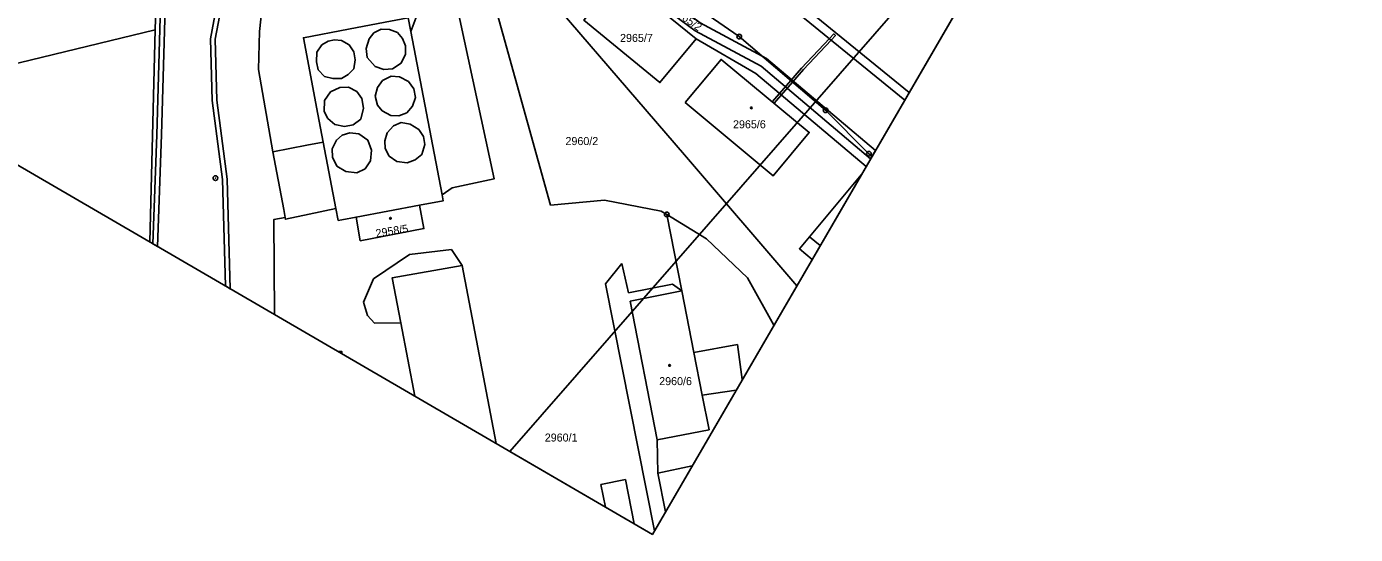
# Model space of a CAD drawing. Extents: x -621168 to -620292, y -1122748 to -1122069.
# Drawn here: x -620574.6 to -620292.4, y -1122748.2 to -1122640.4 of the extents above; entities that cross this region are included whole.
import ezdxf

# ---------------------------------------------------------------- set-up
doc = ezdxf.new("R2010")
doc.units = 0
for name, color, linetype in [('Hranice parcel', 7, 'Continuous'), ('Parcelní čísla', 7, 'Continuous'), ('Rámečky', 7, 'Continuous'), ('Rámečky-tisk', 7, 'Continuous'), ('Vnitřní kresba', 7, 'Continuous'), ('Věcná břemena k části', 7, 'Continuous'), ('Značky bodu BP', 7, 'Continuous'), ('Značky budov', 7, 'Continuous')]:
    doc.layers.add(name, color=color, linetype=linetype)

msp = doc.modelspace()

# ---------------------------------------------------------------- linework, layer by layer
at = {"layer": 'Hranice parcel'}
for p, q in [((-620546.5, -1122612), (-620547.23, -1122641.1)), ((-620547.23, -1122641.1), (-620602.67, -1122654.54)), ((-620547.23, -1122641.1), (-620548.37, -1122686.11)), ((-620435.41, -1122696.52), (-620438.61, -1122680.28)), ((-620440.5, -1122735.14), (-620440.62, -1122728.09))]:
    msp.add_line(p, q, dxfattribs=at)
for points in [[(-620485.21, -1122574.33), (-620466.94, -1122589.51), (-620387.14, -1122654.39)], [(-620502.69, -1122605.61), (-620503.19, -1122607.95), (-620524.52, -1122636.25), (-620525.13, -1122641.47), (-620525.33, -1122649.53), (-620522.29, -1122666.99)], [(-620388.08, -1122656.01), (-620420.38, -1122629.64), (-620446.79, -1122609.88)], [(-620410.99, -1122695.4), (-620434.88, -1122667.63), (-620473.14, -1122623.15)], [(-620452.73, -1122622.13), (-620423.22, -1122642.55), (-620404.9, -1122658.18), (-620395.68, -1122667.41), (-620395.02, -1122667.94)], [(-620486.3, -1122676.15), (-620484.21, -1122674.6), (-620475.28, -1122672.75), (-620485.31, -1122626.04)], [(-620438.61, -1122680.28), (-620439.78, -1122679.56), (-620451.85, -1122677.25), (-620463.28, -1122678.3), (-620478.32, -1122624.38)], [(-620432.38, -1122643.03), (-620440.08, -1122652.3), (-620456.23, -1122639.05), (-620450.04, -1122631.61)], [(-620450.04, -1122631.61), (-620448.58, -1122629.86), (-620432.38, -1122643.03)], [(-620522.29, -1122666.99), (-620515.05, -1122665.61), (-620511.55, -1122664.94), (-620512.68, -1122659.03), (-620515.78, -1122642.8), (-620506.17, -1122640.97), (-620499.9, -1122639.77), (-620493.5, -1122638.55), (-620492.94, -1122641.47), (-620486.3, -1122676.15)], [(-620396.27, -1122670.08), (-620419.73, -1122650.41), (-620432.38, -1122643.03)], [(-620434.7, -1122656.53), (-620427.07, -1122647.39), (-620408.37, -1122662.86), (-620416.01, -1122672.06), (-620434.7, -1122656.53)], [(-620522.29, -1122666.99), (-620519.96, -1122679.22), (-620519.64, -1122680.92)], [(-620407.74, -1122689.82), (-620410.45, -1122687.55), (-620408.32, -1122685), (-620397.34, -1122671.88), (-620397.32, -1122671.9)], [(-620519.64, -1122680.92), (-620519.58, -1122681.29), (-620514.56, -1122680.24), (-620508.86, -1122679.05), (-620508.38, -1122681.54), (-620507.59, -1122681.39), (-620504.59, -1122680.83), (-620503.71, -1122685.86), (-620490.19, -1122683.29), (-620491.13, -1122678.32), (-620486.07, -1122677.38), (-620486.3, -1122676.15)], [(-620519.64, -1122680.92), (-620522.03, -1122681.32), (-620521.9, -1122701.5)], [(-620438.61, -1122680.28), (-620430.21, -1122685.42), (-620421.46, -1122693.76), (-620415.87, -1122703.8)], [(-620492.12, -1122718.82), (-620495.08, -1122703.28), (-620496.9, -1122693.7), (-620482.03, -1122691.1)], [(-620482.03, -1122691.1), (-620474.85, -1122728.86)], [(-620440.62, -1122728.09), (-620446.38, -1122698.69), (-620435.41, -1122696.52)], [(-620440.62, -1122728.09), (-620429.62, -1122725.94), (-620431.07, -1122718.59), (-620432.85, -1122709.54), (-620435.41, -1122696.52)], [(-620508.34, -1122709.39), (-620507.61, -1122709.36), (-620507.58, -1122709.83)], [(-620433.21, -1122733.63), (-620440.5, -1122735.14)], [(-620438.86, -1122743.34), (-620440.5, -1122735.14)]]:
    msp.add_lwpolyline(points, dxfattribs=at)
at = {"layer": 'Rámečky'}
msp.add_line((-620351.12, -1122592.44), (-620471.94, -1122730.56), dxfattribs=at)
msp.add_lwpolyline([(-620471.94, -1122730.56), (-620441.66, -1122748.16), (-620351.12, -1122592.44)], dxfattribs=at)
at = {"layer": 'Rámečky-tisk'}
msp.add_line((-620351.12, -1122592.44), (-620471.94, -1122730.56), dxfattribs=at)
for points in [[(-621018.54, -1122069.17), (-621167.83, -1122325.92), (-620441.66, -1122748.16)], [(-620441.66, -1122748.16), (-620292.37, -1122491.41), (-621018.54, -1122069.17)], [(-620471.94, -1122730.56), (-620441.66, -1122748.16), (-620351.12, -1122592.44)]]:
    msp.add_lwpolyline(points, dxfattribs=at)
at = {"layer": 'Vnitřní kresba'}
for p, q in [((-620487.46, -1122626.56), (-620492.94, -1122641.47)), ((-620510.52, -1122643.55), (-620509.2, -1122643.23)), ((-620509.2, -1122643.23), (-620507.65, -1122643.39)), ((-620502.44, -1122645.1), (-620501.82, -1122643)), ((-620501.82, -1122643), (-620500.81, -1122641.76)), ((-620500.81, -1122641.76), (-620499.26, -1122640.98)), ((-620499.26, -1122640.98), (-620497.47, -1122641.06)), ((-620497.47, -1122641.06), (-620495.76, -1122641.68)), ((-620495.76, -1122641.68), (-620494.75, -1122642.92)), ((-620494.75, -1122642.92), (-620494.06, -1122644.48)), ((-620513, -1122647.9), (-620512.93, -1122645.88)), ((-620512.93, -1122645.88), (-620511.84, -1122644.32)), ((-620511.84, -1122644.32), (-620510.52, -1122643.55)), ((-620507.65, -1122643.39), (-620506.09, -1122644.32)), ((-620506.09, -1122644.32), (-620505.08, -1122645.8)), ((-620505.08, -1122645.8), (-620504.77, -1122647.51)), ((-620502.21, -1122646.96), (-620502.44, -1122645.1)), ((-620494.06, -1122644.48), (-620494.06, -1122646.26)), ((-620512.62, -1122649.6), (-620513, -1122647.9)), ((-620504.77, -1122647.51), (-620505.08, -1122649.37)), ((-620500.5, -1122648.9), (-620502.21, -1122646.96)), ((-620498.71, -1122649.52), (-620500.5, -1122648.9)), ((-620494.99, -1122648.21), (-620496.85, -1122649.37)), ((-620494.06, -1122646.26), (-620494.99, -1122648.21)), ((-620511.3, -1122651), (-620512.62, -1122649.6)), ((-620509.51, -1122651.47), (-620511.3, -1122651)), ((-620507.65, -1122651.47), (-620509.51, -1122651.47)), ((-620506.25, -1122650.61), (-620507.65, -1122651.47)), ((-620505.08, -1122649.37), (-620506.25, -1122650.61)), ((-620500.03, -1122653.33), (-620498.95, -1122651.85)), ((-620498.95, -1122651.85), (-620497.16, -1122650.92)), ((-620496.85, -1122649.37), (-620498.71, -1122649.52)), ((-620497.16, -1122650.92), (-620495.38, -1122651.08)), ((-620495.38, -1122651.08), (-620493.43, -1122652.09)), ((-620511.3, -1122656.13), (-620510.05, -1122654.26)), ((-620510.05, -1122654.26), (-620508.03, -1122653.33)), ((-620508.03, -1122653.33), (-620506.17, -1122653.25)), ((-620506.17, -1122653.25), (-620504.46, -1122654.18)), ((-620504.46, -1122654.18), (-620503.37, -1122655.66)), ((-620500.5, -1122655.19), (-620500.03, -1122653.33)), ((-620493.43, -1122652.09), (-620492.35, -1122653.64)), ((-620492.35, -1122653.64), (-620491.96, -1122655.5)), ((-620511.37, -1122658.46), (-620511.3, -1122656.13)), ((-620503.37, -1122655.66), (-620502.99, -1122657.76)), ((-620500.03, -1122657.06), (-620500.5, -1122655.19)), ((-620499.03, -1122658.3), (-620500.03, -1122657.06)), ((-620492.58, -1122657.29), (-620493.82, -1122658.69)), ((-620491.96, -1122655.5), (-620492.58, -1122657.29)), ((-620510.6, -1122659.93), (-620511.37, -1122658.46)), ((-620509.12, -1122661.17), (-620510.6, -1122659.93)), ((-620503.61, -1122660.09), (-620505.24, -1122661.25)), ((-620502.99, -1122657.76), (-620503.61, -1122660.09)), ((-620497.24, -1122659.31), (-620499.03, -1122658.3)), ((-620495.53, -1122659.39), (-620497.24, -1122659.31)), ((-620493.82, -1122658.69), (-620495.53, -1122659.39)), ((-620507.02, -1122661.64), (-620509.12, -1122661.17)), ((-620507.57, -1122663.43), (-620505.94, -1122662.96)), ((-620505.24, -1122661.25), (-620507.02, -1122661.64)), ((-620505.94, -1122662.96), (-620504, -1122663.19)), ((-620498.48, -1122664.67), (-620498.02, -1122662.96)), ((-620498.02, -1122662.96), (-620496.62, -1122661.48)), ((-620496.62, -1122661.48), (-620494.99, -1122660.79)), ((-620494.99, -1122660.79), (-620493.12, -1122661.1)), ((-620493.12, -1122661.1), (-620491.26, -1122662.26)), ((-620491.26, -1122662.26), (-620490.25, -1122663.74)), ((-620508.86, -1122679.05), (-620511.55, -1122664.94)), ((-620509.67, -1122666.38), (-620508.73, -1122664.51)), ((-620508.73, -1122664.51), (-620507.57, -1122663.43)), ((-620504, -1122663.19), (-620502.06, -1122664.51)), ((-620502.06, -1122664.51), (-620501.28, -1122666.61)), ((-620498.41, -1122666.3), (-620498.48, -1122664.67)), ((-620490.02, -1122665.44), (-620490.64, -1122667.54)), ((-620490.25, -1122663.74), (-620490.02, -1122665.44)), ((-620509.59, -1122668.16), (-620509.67, -1122666.38)), ((-620508.66, -1122670.03), (-620509.59, -1122668.16)), ((-620501.28, -1122666.61), (-620501.51, -1122668.94)), ((-620497.55, -1122667.93), (-620498.41, -1122666.3)), ((-620495.92, -1122669.02), (-620497.55, -1122667.93)), ((-620492.04, -1122668.71), (-620493.75, -1122669.33)), ((-620490.64, -1122667.54), (-620492.04, -1122668.71)), ((-620506.79, -1122671.19), (-620508.66, -1122670.03)), ((-620504.46, -1122671.42), (-620506.79, -1122671.19)), ((-620502.68, -1122670.57), (-620504.46, -1122671.42)), ((-620501.51, -1122668.94), (-620502.68, -1122670.57)), ((-620493.75, -1122669.33), (-620495.92, -1122669.02)), ((-620504.59, -1122680.83), (-620491.13, -1122678.32)), ((-620406.05, -1122686.9), (-620408.32, -1122685)), ((-620493.22, -1122688.81), (-620484.3, -1122687.75)), ((-620484.3, -1122687.75), (-620482.03, -1122691.1)), ((-620500.9, -1122693.92), (-620493.22, -1122688.81)), ((-620448.12, -1122690.72), (-620451.61, -1122694.97)), ((-620446.75, -1122696.88), (-620448.12, -1122690.72)), ((-620503.01, -1122698.89), (-620500.9, -1122693.92)), ((-620451.61, -1122694.97), (-620441.23, -1122747.41)), ((-620437.36, -1122695.04), (-620446.75, -1122696.88)), ((-620437.36, -1122695.04), (-620435.41, -1122696.52)), ((-620502.18, -1122701.71), (-620503.01, -1122698.89)), ((-620500.67, -1122703.36), (-620502.18, -1122701.71)), ((-620495.08, -1122703.28), (-620500.67, -1122703.36)), ((-620432.85, -1122709.54), (-620423.56, -1122707.88)), ((-620423.56, -1122707.88), (-620422.57, -1122715.32)), ((-620423.88, -1122717.57), (-620431.07, -1122718.59)), ((-620447.35, -1122736.5), (-620452.59, -1122737.55)), ((-620445.54, -1122745.91), (-620447.35, -1122736.5)), ((-620451.65, -1122742.35), (-620452.59, -1122737.55))]:
    msp.add_line(p, q, dxfattribs=at)
at = {"layer": 'Věcná břemena k části'}
for p, q in [((-620395.34, -1122668.49), (-620394.32, -1122666.74)), ((-620547.72, -1122686.49), (-620546.73, -1122687.07)), ((-620532.32, -1122695.44), (-620531.3, -1122696.04))]:
    msp.add_line(p, q, dxfattribs=at)
for points in [[(-620394.32, -1122666.74), (-620417.42, -1122647.16), (-620431.52, -1122639.64), (-620457.44, -1122620.38), (-620448.45, -1122606.75), (-620478.4, -1122581.98), (-620488.36, -1122586.21), (-620487.32, -1122587.95), (-620478.74, -1122584.3), (-620451.11, -1122607.15), (-620460.16, -1122620.86), (-620432.6, -1122641.34), (-620418.54, -1122648.82), (-620395.34, -1122668.49)], [(-620545.88, -1122628.46), (-620546.91, -1122663.38), (-620547.72, -1122686.49)], [(-620546.73, -1122687.07), (-620545.91, -1122663.42), (-620544.9, -1122629)], [(-620534.2, -1122636.18), (-620535.53, -1122643.03), (-620535.16, -1122656.08), (-620532.94, -1122672.87), (-620532.32, -1122695.44)], [(-620531.3, -1122696.04), (-620531.94, -1122672.79), (-620534.16, -1122656), (-620534.53, -1122643.11), (-620533.24, -1122636.48)]]:
    msp.add_lwpolyline(points, dxfattribs=at)
for points in [[(-620414.7, -1122654.63), (-620414.31, -1122654.95), (-620411.9, -1122652.2), (-620409.58, -1122649.55), (-620403.69, -1122643.27), (-620402.81, -1122642.33), (-620403.17, -1122641.99), (-620404.07, -1122642.95), (-620409.97, -1122649.21), (-620412.29, -1122651.87)], [(-620415.83, -1122656.69), (-620414.31, -1122654.95), (-620414.7, -1122654.63), (-620416.22, -1122656.37)]]:
    msp.add_lwpolyline(points, close=True, dxfattribs=at)
at = {"layer": 'Značky bodu BP'}
for centre, radius in [((-620423.22, -1122642.55), 0.5), ((-620423.22, -1122642.55), 0.0303), ((-620404.9, -1122658.18), 0.5), ((-620404.9, -1122658.18), 0.0303), ((-620395.68, -1122667.41), 0.5), ((-620395.68, -1122667.41), 0.0303), ((-620534.45, -1122672.58), 0.5), ((-620534.45, -1122672.58), 0.0303), ((-620438.61, -1122680.28), 0.5), ((-620438.61, -1122680.28), 0.0303)]:
    msp.add_circle(centre, radius, dxfattribs=at)
at = {"layer": 'Značky budov'}
for centre in [(-620420.66, -1122657.67), (-620497.29, -1122681.09), (-620438.02, -1122712.31)]:
    msp.add_circle(centre, 0.175, dxfattribs=at)

# ---------------------------------------------------------------- texts
at = {"layer": 'Parcelní čísla'}
for s, rotation, p in [('2965/2', 325, (-620437.6, -1122637.48)), ('2958/5', 9, (-620500.28, -1122685.15))]:
    msp.add_text(s, height=1.7, rotation=rotation, dxfattribs=at).set_placement(p)
for s, p in [('2965/7', (-620448.53, -1122643.68)), ('2965/6', (-620424.54, -1122662)), ('2960/2', (-620460.12, -1122665.56)), ('2960/6', (-620440.22, -1122716.49)), ('2960/1', (-620464.52, -1122728.46))]:
    msp.add_text(s, height=1.7, dxfattribs=at).set_placement(p)

doc.saveas('drawing.dxf')
